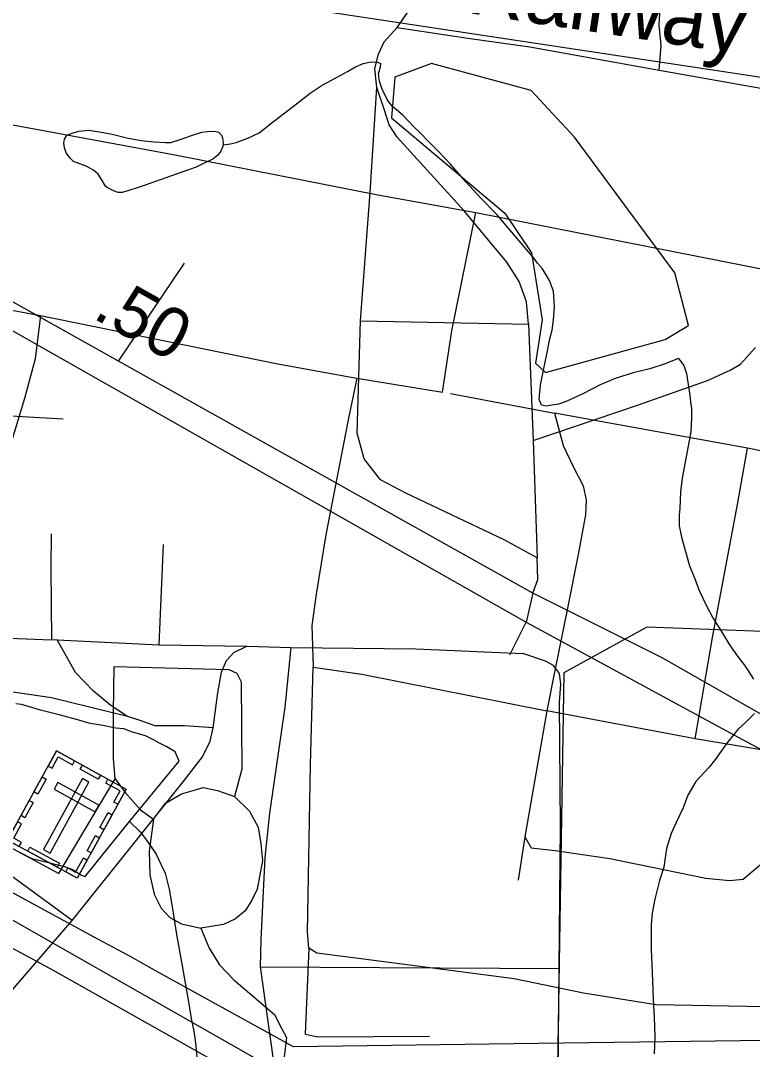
# Model space of a CAD drawing. Extents: x 2169602 to 2449496, y 721995 to 810662.
# Drawn here: x 2389956 to 2391790, y 761759 to 764336 of the extents above; entities that cross this region are included whole.
import ezdxf

# ---------------------------------------------------------------- set-up
doc = ezdxf.new("R2010")
doc.units = 0
doc.layers.add('Default', color=7, linetype='Continuous')

msp = doc.modelspace()

# ---------------------------------------------------------------- linework, layer by layer
at = {"layer": 'Default'}
for p, q in [((2391232.3, 764269.9), (2391556, 764212.1)), ((2391556, 764212.1), (2391850.8, 764159.6)), ((2390201.3, 763483.2), (2390367, 763728.3)), ((2389393.7, 763710.1), (2390005.9, 763597)), ((2390807.8, 763584.1), (2391228.7, 763575.5)), ((2390798.9, 763440.6), (2391013.1, 763405.3)), ((2391033, 763401.7), (2391293.5, 763352.9)), ((2391777.2, 763265.2), (2391293.5, 763352.9)), ((2390303.2, 762772.1), (2390314.1, 763023.5)), ((2391239.9, 762901.6), (2391223.1, 762829.4)), ((2391182, 762747.2), (2391223.1, 762829.4)), ((2390048.3, 762784.8), (2390034.7, 762783.9)), ((2390048.3, 762784.8), (2390303.2, 762772.1)), ((2390303.2, 762772.1), (2390523, 762769.4)), ((2390523, 762769.4), (2390633.3, 762765.8)), ((2391274.5, 762606.9), (2391219.3, 762291.4)), ((2391646.1, 762537.3), (2391274.5, 762606.9)), ((2390052, 762200), (2390193, 762436.9)), ((2390085.3, 762082.2), (2389745.4, 762330)), ((2391219.3, 762291.4), (2391203, 762182.9)), ((2389927.2, 762267), (2390052, 762200)), ((2389870.1, 761832.7), (2390085.3, 762082.2)), ((2390678.6, 762012.9), (2390669.6, 761797.7)), ((2390556.4, 761965.6), (2391305.1, 761962))]:
    msp.add_line(p, q, dxfattribs=at)
for points in [[(2386341.5, 765606), (2386685.3, 765448.6), (2387371.5, 765146.4), (2387823.3, 764945.6), (2388085.7, 764838.9), (2388237.7, 764783.6), (2388424, 764732.4), (2388640.1, 764677.4), (2388810.3, 764648.1), (2388810.3, 764648.4), (2389850.9, 764490.4), (2391789.9, 764197.4), (2393113.8, 763990.4)], [(2390899.6, 764318.8), (2390933.9, 764367.6), (2390961, 764411), (2390970.1, 764459.8), (2390984.6, 764496), (2390990.4, 764520.3)], [(2391556, 764212.1), (2391561.4, 764273.6), (2391556, 764324.2), (2391557.8, 764353.1), (2391556, 764369.4), (2391545.2, 764387.5), (2391523.5, 764394.7), (2391478.2, 764382.1), (2391451.1, 764376.6), (2391418.6, 764383.9), (2391349.8, 764427.3), (2391299.2, 764439.9), (2391167.2, 764479.7)], [(2390848.9, 764168.7), (2390843.5, 764215.7), (2390852.5, 764251.9), (2390867, 764282.6), (2390899.6, 764318.8)], [(2390899.6, 764318.8), (2391076.8, 764291.6), (2391232.3, 764269.9)], [(2390464.1, 764024.8), (2390482.3, 764027), (2390496.1, 764030.9), (2390525.8, 764041.1), (2390554.1, 764055), (2390589.8, 764083.3), (2390640, 764121.6), (2390681.4, 764153.8), (2390711.6, 764174), (2390747.3, 764193.7), (2390775.6, 764208.1), (2390795.5, 764220.1), (2390814.9, 764228.1), (2390834.8, 764232.4), (2390849.4, 764232.2), (2390858.8, 764228.4)], [(2391604.2, 763489.8), (2391568.3, 763475.8), (2391532.6, 763463.7), (2391490.6, 763453.5), (2391446.1, 763439.5), (2391408.6, 763423.3), (2391364.5, 763401.1), (2391324.9, 763382.8), (2391304.8, 763374.9), (2391286.8, 763372.7), (2391272.6, 763370.4), (2391261.1, 763372.6), (2391255, 763386.5), (2391258.9, 763422.4), (2391266.5, 763460.6), (2391274.5, 763500.4), (2391282, 763538.6), (2391287.8, 763560.4), (2391291.7, 763586.5), (2391294.1, 763618.6), (2391291.7, 763658.4), (2391281.2, 763684.7), (2391263.4, 763714.5), (2391251.1, 763728.2), (2391242.9, 763740.3), (2391149, 763849.9), (2391108.8, 763891.7), (2391072.5, 763931.2), (2391032.5, 763977.4), (2391004.4, 764007.2), (2390979.8, 764031.2), (2390955.6, 764056.8), (2390941.9, 764069), (2390913.8, 764098.8), (2390887.7, 764120.6), (2390875.4, 764136.6), (2390861.7, 764164.3), (2390855.3, 764184.3), (2390853.3, 764202.5), (2390857.6, 764220.5), (2390858.8, 764228.4)], [(2391271.4, 763454.6), (2391571.4, 763537.1), (2391629.4, 763572), (2391595.4, 763703.9), (2391343.6, 764043.6), (2391235.5, 764160.7), (2390985.6, 764228.1), (2390893.5, 764193.9), (2390885.5, 764092.4), (2391169.5, 763853.7), (2391236.6, 763753.9), (2391262.6, 763586.1), (2391246.4, 763478.2), (2391271.4, 763454.6)], [(2393587.2, 760051.8), (2393538.6, 760080.4), (2392907.2, 760430.4), (2392607.1, 760604.7), (2392161.9, 760840.1), (2391730.4, 761078), (2390962.6, 761500.1), (2390605.2, 761701.9), (2389990.5, 762051.8), (2389856.7, 762127.7), (2389737.8, 762198.8), (2389440.2, 762351.9), (2389076.5, 762551.2), (2388547.4, 762852.9), (2388224.1, 763014.5), (2387185.5, 763596), (2386852.4, 763781.6), (2386637.1, 763912.4), (2386426.2, 764027.4), (2386153.7, 764163.9)], [(2389477.8, 764163.1), (2389885.6, 764084.4), (2390347.7, 763998.5), (2390851.3, 763899.9), (2391096.6, 763855.4)], [(2390807.8, 763584.1), (2390831.7, 763905.6), (2390848.9, 764168.7)], [(2391228.7, 763575.5), (2391223.3, 763631.6), (2391205.2, 763682.2), (2391174.4, 763731), (2391067.7, 763859.4), (2390899.6, 764043.9), (2390879.7, 764074.6), (2390867, 764114.4), (2390848.9, 764168.7)], [(2386150.4, 764102.4), (2386756.5, 763764.2), (2388207.3, 762942.2), (2388747.6, 762648.7), (2389706.7, 762136.5), (2390036.6, 761958.6), (2390589, 761647.1), (2390889.1, 761482.7), (2391705.4, 761033.1), (2392100.8, 760810.2), (2392574.7, 760557.4), (2392899.7, 760371.9), (2393558.4, 760007.1)], [(2396603, 759939), (2396554.4, 759967.6), (2395923, 760317.6), (2395622.9, 760491.9), (2395177.7, 760727.3), (2394746.2, 760965.1), (2393978.4, 761387.3), (2393621, 761589.1), (2393006.3, 761938.9), (2392872.5, 762014.9), (2392753.6, 762085.9), (2392456, 762239.1), (2392092.4, 762438.4), (2391563.2, 762740), (2391239.9, 762901.6), (2390201.3, 763483.2), (2389868.2, 763668.8), (2389653, 763799.6), (2389442, 763914.6), (2389169.5, 764051.1)], [(2390464.1, 764024.8), (2390462.2, 764018.6), (2390458.3, 764008.7), (2390450.3, 763998.5), (2390438, 763988.6), (2390416.5, 763978.5), (2390396.4, 763968.5), (2390360.5, 763956.1), (2390268.7, 763923.8), (2390250.8, 763918), (2390224.8, 763909.7), (2390210.8, 763905.7), (2390200.8, 763905.7), (2390189.1, 763909.5), (2390172.9, 763917.6), (2390169, 763921.4), (2390160.6, 763935.3), (2390150.6, 763951.4), (2390138.7, 763961.3), (2390120.6, 763971.3), (2390104.6, 763977), (2390088.6, 763983.1), (2390080.6, 763991.2), (2390070.2, 764004.9), (2390066.3, 764016.9), (2390064.4, 764028.9), (2390066.1, 764038.8), (2390072.4, 764049.2), (2390087.8, 764055), (2390102.2, 764059.3), (2390126.4, 764061.3), (2390154.3, 764057.5), (2390185.8, 764051.5), (2390226, 764041.8), (2390258.4, 764035.6), (2390290.6, 764032), (2390318.3, 764030.3), (2390332.4, 764030.2), (2390355.8, 764038.4), (2390384.3, 764048.3), (2390410.4, 764056.5), (2390424.3, 764058.5), (2390442.1, 764058.6), (2390452.4, 764056.6), (2390460, 764048.6), (2390462, 764042.6), (2390463.9, 764028.9), (2390464.1, 764024.8)], [(2389166.2, 763989.6), (2389772.3, 763651.3), (2391223.1, 762829.4), (2391763.5, 762535.9), (2392722.5, 762023.7), (2393052.4, 761845.8), (2393604.8, 761534.3), (2393905, 761369.9), (2394721.3, 760920.3), (2395116.7, 760697.4), (2395590.5, 760444.6), (2395915.6, 760259), (2396574.3, 759894.3)], [(2391013.1, 763405.3), (2391036.7, 763559.1), (2391096.6, 763855.4)], [(2391096.6, 763855.4), (2391837.8, 763709.2), (2392261.8, 763637.7), (2392281.7, 763630.5), (2392298, 763616), (2392305.2, 763594.3), (2392296.2, 763549.1), (2392256.4, 763361), (2392215.7, 763168.4)], [(2390005.9, 763597), (2389993.2, 763488.5), (2389966.1, 763389.1), (2389887.4, 763133.2), (2389853.1, 763069.9), (2389824.1, 763037.3), (2389788, 763019.3), (2389556.5, 762945.1)], [(2390005.9, 763597), (2390600.8, 763475.9), (2390798.9, 763440.6)], [(2391250.5, 762990.1), (2391168.1, 763035.7), (2390921.7, 763152), (2390858.2, 763185.6), (2390817.1, 763237.9), (2390799.7, 763302.6), (2390807.8, 763584.1)], [(2391228.7, 763575.5), (2391240.5, 763284)], [(2391240.5, 763284), (2391501.8, 763373), (2391677.2, 763434.5), (2391734.1, 763460.7), (2391759.4, 763475.2), (2391797.4, 763516.8)], [(2391604.2, 763489.8), (2391618.1, 763471.9), (2391624.1, 763451.9), (2391628.4, 763424.1), (2391632.5, 763397.9), (2391634.7, 763380.1), (2391636.8, 763364), (2391637, 763340), (2391635.1, 763306.2), (2391613.6, 763190.2), (2391609.7, 763156), (2391607.9, 763114), (2391606, 763098.1), (2391606, 763070.1), (2391612, 763042), (2391632.3, 762970), (2391642.5, 762944.2), (2391656.5, 762908.4), (2391674.3, 762870.4), (2391690.5, 762840.3), (2391710.4, 762808.2), (2391732.3, 762772.4), (2391752.4, 762744.2), (2391768.6, 762722.2), (2391774.6, 762714.4), (2391792.4, 762686.6)], [(2390798.9, 763440.6), (2390777.2, 763335.7), (2390721.1, 763048.2), (2390696.7, 762899), (2390685.8, 762821.2), (2390689.4, 762716.3)], [(2388790.5, 763400.6), (2389072.6, 763384.3), (2389757.1, 763356.3), (2390062.7, 763338.2)], [(2391293.5, 763352.9), (2391315.2, 763271.5), (2391340.5, 763219.1), (2391365.8, 763170.3), (2391373, 763135.9), (2391371.2, 763097.9), (2391353.1, 762998.5), (2391326, 762864.6), (2391294.4, 762708.2), (2391274.5, 762606.9)], [(2391240.5, 763284), (2391250.5, 762990.1)], [(2391646.1, 762537.3), (2391689.5, 762790.5), (2391751.9, 763124.1), (2391777.2, 763265.2)], [(2392215.7, 763168.4), (2392120.8, 763194.7), (2391777.2, 763265.2)], [(2390034.7, 762783.9), (2390032.9, 762966.5), (2390033.8, 763050.6)], [(2391239.9, 762901.6), (2391251.8, 762936.5), (2391250.5, 762990.1)], [(2393165.7, 761922.9), (2392899.5, 762066.6), (2392870, 762082.9), (2392691.2, 762182.1), (2392674, 762191.7), (2392811.2, 762462.9), (2392963, 762763.4), (2392384, 762778.8), (2392015.5, 762798.5), (2391525.2, 762816.4), (2391317.2, 762702.1), (2391291, 761093.9), (2391306, 761091.6), (2391316, 761088.3), (2391321.2, 761086.2), (2391334.2, 761082), (2391343, 761079.6)], [(2393165.7, 761922.9), (2392899.5, 762066.6), (2392870, 762082.9), (2392691.2, 762182.1), (2392674, 762191.7), (2392811.2, 762462.9), (2392963, 762763.4), (2392384, 762778.8), (2392015.5, 762798.5), (2391525.2, 762816.4), (2391317.2, 762702.1), (2391291, 761093.9), (2391306, 761091.6), (2391316, 761088.3), (2391321.2, 761086.2), (2391334.2, 761082), (2391343, 761079.6)], [(2390034.7, 762783.9), (2389754.4, 762794.8), (2389721.8, 762789.3), (2389698.3, 762782.1)], [(2390223.7, 762593.1), (2390182.1, 762620.2), (2390138.7, 762656.4), (2390093.5, 762703.4), (2390048.3, 762784.8)], [(2390438.9, 762564.2), (2390450.6, 762651.9), (2390459.7, 762704.3), (2390472.3, 762733.3), (2390490.4, 762753.2), (2390523, 762769.4)], [(2390633.3, 762765.8), (2390617.9, 762616.6), (2390579.9, 762350.8), (2390568.2, 762239.6), (2390558.2, 762034.3), (2390556.4, 761965.6)], [(2390633.3, 762765.8), (2390946.1, 762762.2), (2391214.7, 762750.4)], [(2391305.1, 761962), (2391308.7, 762318.2), (2391306, 762628.4), (2391309.6, 762673.6), (2391306, 762700.7), (2391291.5, 762720.6), (2391271.6, 762731.5), (2391214.7, 762750.4)], [(2390193, 762436.9), (2390189.4, 762487.6), (2390189.4, 762603.3), (2390190.3, 762718.2)], [(2390190.3, 762718.2), (2390477.9, 762710.9), (2390497.8, 762701.9), (2390508.6, 762680.2), (2390510.4, 762461.4), (2390492.3, 762392.6)], [(2390678.6, 762012.9), (2390675, 762052.7), (2390682.2, 762472.2), (2390689.4, 762716.3)], [(2390689.4, 762716.3), (2390811.5, 762699.2), (2391274.5, 762606.9)], [(2390223.7, 762593.1), (2390033.8, 762640.1), (2389919.9, 762656.4), (2389854.8, 762665.5), (2389809.5, 762660), (2389760.7, 762645.6), (2389733.6, 762629.3), (2389699.2, 762596.7)], [(2390229.5, 762330.4), (2390353.2, 762480.8), (2390343.1, 762504.7), (2390323, 762516.6), (2390302.9, 762526.6), (2390289, 762534.4), (2390268.9, 762544.3), (2390236.5, 762554), (2390214.5, 762562.2), (2390194.9, 762564), (2390162.7, 762570.1), (2390130.5, 762575.8), (2390096.4, 762585.8), (2390052.5, 762597.3), (2390006.4, 762609.2), (2389978.3, 762617), (2389958.6, 762622.9), (2389944.5, 762625)], [(2390438.9, 762564.2), (2390366.5, 762569.6), (2390292.4, 762569.6), (2390258, 762582.3), (2390223.7, 762593.1)], [(2391795.1, 762600.6), (2391773.1, 762578.4), (2391753.2, 762560.3), (2391725.4, 762526.4), (2391697.5, 762486), (2391681.3, 762466.1), (2391647.6, 762429.8), (2391628, 762395.9), (2391616.3, 762364), (2391598.8, 762327.7), (2391586.5, 762300), (2391574.6, 762262), (2391567.5, 762215.7), (2391557, 762181.9), (2391545.5, 762135.8), (2391538.4, 762100), (2391536.3, 762071.9), (2391536.1, 762009.9), (2391539, 761930), (2391541, 761884.2), (2391543.1, 761840.1), (2391545.3, 761790.3), (2391543.9, 761748.3)], [(2390085.3, 762082.2), (2390246.3, 762283), (2390363.8, 762429.5), (2390411.7, 762491.8), (2390431.6, 762531.6), (2390438.9, 762564.2)], [(2391219.3, 762291.4), (2391235.6, 762264.2), (2391295.3, 762257), (2391432.7, 762237.1), (2391673.2, 762188.3), (2391732, 762182), (2391766.3, 762185.6), (2391847.7, 762254.3), (2391907.4, 762317.6), (2391934.5, 762350.1), (2391938.1, 762377.3), (2391938.1, 762420.7), (2391934.5, 762453.2), (2391923.7, 762478.5), (2391902, 762494.8), (2391646.1, 762537.3)], [(2392912.7, 762516.7), (2392875.7, 762340), (2392829.4, 762132.1), (2392824.9, 762099.4), (2392721.2, 762064.4), (2392417.9, 761962.1), (2392195.7, 761887.1), (2391949.4, 761804.1), (2391886.2, 761782.7), (2391506.4, 761777.5), (2391252.9, 761774), (2390640.2, 761765.6), (2390304.7, 761950.4), (2390226.9, 761994.2), (2390224.9, 761995.3), (2390149.9, 762035.7), (2389883.7, 762179.4)], [(2392912.7, 762516.7), (2392875.7, 762340), (2392829.4, 762132.1), (2392824.9, 762099.4), (2392721.2, 762064.4), (2392417.9, 761962.1), (2392195.7, 761887.1), (2391949.4, 761804.1), (2391886.2, 761782.7), (2391506.4, 761777.5), (2391252.9, 761774), (2390640.2, 761765.6), (2390304.7, 761950.4), (2390226.9, 761994.2), (2390224.9, 761995.3), (2390149.9, 762035.7), (2389883.7, 762179.4)], [(2390193, 762436.9), (2390218.4, 762402.6), (2390256.3, 762359.2), (2390288.9, 762335.7)], [(2390288.9, 762335.7), (2390319.6, 762375.5), (2390359.4, 762399), (2390388.4, 762408), (2390413.7, 762415.2), (2390449.8, 762408), (2390492.3, 762392.6)], [(2390492.3, 762392.6), (2390529.4, 762355.6), (2390551.1, 762315.8), (2390558.3, 762274.2), (2390562, 762232.6), (2390549.3, 762160.3), (2390534.8, 762131.3), (2390518.6, 762106), (2390495, 762086.1), (2390464.3, 762071.7), (2390408.2, 762062.6)], [(2389950, 762255.1), (2389984.1, 762237.3), (2390026.1, 762227.3), (2390066.1, 762217.6), (2390086.6, 762209.7), (2390108.5, 762195.8), (2390118.4, 762191.9), (2390229.5, 762330.4)], [(2390229.5, 762330.4), (2390255.8, 762304.5), (2390273.8, 762280.3), (2390296.1, 762248.5), (2390308, 762222.8), (2390318.3, 762200.6), (2390328.3, 762160.9), (2390336.5, 762111), (2390346.8, 762047), (2390361.4, 761968.9), (2390369.6, 761921), (2390377.8, 761873.2), (2390383.9, 761836.9), (2390389.9, 761805.2), (2390394.2, 761775.4), (2390398.3, 761731.4), (2390402.4, 761697.5), (2390402.4, 761669.1), (2390402.6, 761647.2), (2390402.4, 761631.4)], [(2390288.9, 762335.7), (2390278, 762256.1), (2390279.8, 762196.4), (2390290.7, 762147.6), (2390308.8, 762113.2), (2390330.5, 762089.7), (2390359.4, 762073.5), (2390408.2, 762062.6)], [(2390408.2, 762062.6), (2390429, 762012.9), (2390454.4, 761971.3), (2390490.5, 761933.3), (2390592.7, 761846.3), (2390610.2, 761812.7), (2390622.6, 761789.1), (2390616.4, 761740.5), (2390605.2, 761701.9)], [(2392112.7, 761873.6), (2391996.9, 761864.6), (2391776.3, 761866.4), (2391547.5, 761870.9), (2391366.7, 761899.9), (2391193.1, 761936), (2390796.1, 761987.6), (2390698.5, 762000.2), (2390678.6, 762012.9)], [(2390556.4, 761965.6), (2390608.9, 761591.3), (2390622.4, 761462), (2390629.7, 761442.1), (2390656.8, 761429.4), (2390738.2, 761427.6), (2391294.2, 761441.2)], [(2391294.2, 761441.2), (2391299.7, 761477.3), (2391303.3, 761698), (2391305.1, 761962)], [(2390669.6, 761797.7), (2390702.1, 761790.4), (2390980.6, 761792.3)]]:
    msp.add_lwpolyline(points, dxfattribs=at)
for points in [[(2390046.1, 762506.9), (2390220.7, 762411.2), (2390098.4, 762187.9), (2389923.8, 762283.6)], [(2390025.3, 762468.9), (2390035.2, 762463.4), (2390050.7, 762491.7), (2390086.3, 762472.2), (2390091.6, 762481.9), (2390046.1, 762506.9)], [(2390111.1, 762471.3), (2390156.5, 762446.4), (2390151, 762436.4), (2390105.6, 762461.3)], [(2389989.6, 762403.9), (2390010.5, 762441.9), (2390020.4, 762436.4), (2389999.6, 762398.4)], [(2390127.6, 762428.8), (2390111.3, 762437.8), (2390013.8, 762259.9), (2390030.2, 762251)], [(2390049.2, 762427.6), (2390040.2, 762411.2), (2390143.5, 762354.6), (2390152.5, 762371)], [(2390199.9, 762373.2), (2390190, 762378.6), (2390205.4, 762406.8), (2390169.9, 762426.3), (2390175.2, 762436.1), (2390220.7, 762411.2)], [(2389957.3, 762344.9), (2389978.1, 762382.9), (2389988.1, 762377.4), (2389967.3, 762339.5)], [(2390154.8, 762314.6), (2390175.6, 762352.5), (2390185.6, 762347.1), (2390164.8, 762309.1)], [(2389952.8, 762267.7), (2389958.3, 762277.8), (2389939, 762288.4), (2389958.4, 762323.8), (2389948.7, 762329.2), (2389923.7, 762283.6)], [(2390123.1, 762256.8), (2390143.9, 762294.7), (2390153.9, 762289.3), (2390133.1, 762251.3)], [(2389979.7, 762266), (2390054.1, 762225.3), (2390048.6, 762215.3), (2389974.2, 762256)], [(2390069.3, 762203.8), (2390074.8, 762213.9), (2390094.1, 762203.3), (2390113.5, 762238.8), (2390123.3, 762233.4), (2390098.4, 762187.9)]]:
    msp.add_lwpolyline(points, close=True, dxfattribs=at)

# ---------------------------------------------------------------- texts
for s, height, rotation, p in [('Railway', 150, 351.409, (2391070.7, 764355.9)), ('.50', 125, 330.7533, (2390133.6, 763592.8))]:
    msp.add_text(s, height=height, rotation=rotation, dxfattribs=at).set_placement(p)

doc.saveas('drawing.dxf')
